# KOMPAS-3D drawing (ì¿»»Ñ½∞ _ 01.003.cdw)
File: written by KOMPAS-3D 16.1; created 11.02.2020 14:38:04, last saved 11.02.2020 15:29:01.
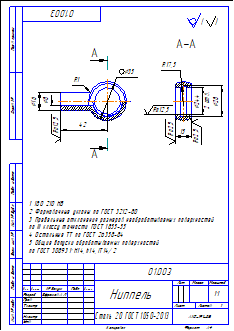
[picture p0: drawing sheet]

Sheet 1: A4, portrait

Title block, sheet 1: name: Ниппель; designation: 01.003; material: Сталь 20 ГОСТ 1050-2013; scale: 1:1; sheets: 1; organisation: АХ2-191-ДБ; sheet format: A4; drawn by: Ефремов А.Л.

Views: Вид 1
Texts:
  Пользователь Windows
  Ra2,5
  Ra12,5
  2. Формовочные уклоны по ГОСТ 3212-80.
  3. Предельные отклонения размеров необрабатываемых поверхностей
  по III классу точности ГОСТ 1855-55.
  4. Остальные ТТ по ГОСТ 26358-84.
  5. Общие допуски обрабатываемых поверхностей
  по ГОСТ 30893.1: Н14, h14, IT14/2.
Dimensions and other numbers on the sheet: 24,4; 2 отв.; 28; 17,5; 8; 16; 42; 35; 15; 1. 180...210 НВ.; 1; 1:1; 01.003; 01.003-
